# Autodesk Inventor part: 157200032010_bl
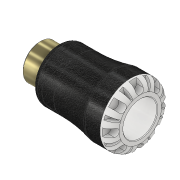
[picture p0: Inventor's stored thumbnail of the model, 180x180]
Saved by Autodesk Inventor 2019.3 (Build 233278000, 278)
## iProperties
Created: 2016-12
Part Number: 157200032010_bl
Material: PVC-Piping
Description: PLASSON G-PLASS BRASS MALE ADAPTOR 32X1"
Document SubType Name: Modeling
Designer: KIM
Mass: 61.7504 g
Surface Area: 140.097 cm^2
Volume: 44.1074 cm^3
Density: 1.4 g/cm^3
Appearance: Black Cast
Author: KIM
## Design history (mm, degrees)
derived "157200.ipt"
feature "Solid1::157200.ipt" dims "ScaleForDerivedMember" = 10
tag "TaggingFeature1"
body "Solid1"
other parameters: "d0" = 95 [user parameter], "d1" = 23.94 [user parameter], "d2" = 32 [user parameter], "d4" = 58 [user parameter], "d6" = 57 [user parameter], "d8" = 49.3 [user parameter], "d13" = 7.2 [user parameter], "d14" = 7.2 [user parameter], "d15" = 0 [user parameter], "d17" = 360 deg [user parameter], "d19" = 8 deg [user parameter], "d20" = 0.64 [user parameter], "d21" = 0.64 [user parameter], "d22" = 8 deg [user parameter], "d24" = 0 [user parameter], "d26" = 360 deg [user parameter], "d32" = 5.8 [user parameter], "d33" = 5.8 [user parameter], "d34" = 33.249 [user parameter], "d38" = 17 [user parameter], "d39" = 0.99747 [user parameter], "d42" = 11.2 [user parameter], "d43" = 7.36 [user parameter], "d45" = 14.112 [user parameter], "d46" = 0 [user parameter], "d59" = 360 deg [user parameter], "d61" = 9.52 [user parameter], "d62" = 0.64 [user parameter], "d64" = 0 [user parameter], "d65" = 0.58 [user parameter], "d68" = 4.57143 [user parameter], "d_" = 32 [user parameter], "E_" = 58 [user parameter], "H_" = 95 [user parameter], "l_" = 57 [user parameter], "R_" = 33.249 [user parameter], "l_2" = 17 [user parameter], "d9" = 9 [user parameter], "d11" = 58 [user parameter]
